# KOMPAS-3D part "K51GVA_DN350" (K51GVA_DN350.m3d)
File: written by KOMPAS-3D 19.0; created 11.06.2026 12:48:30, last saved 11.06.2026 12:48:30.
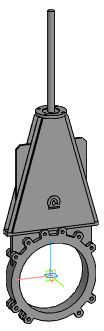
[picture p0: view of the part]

Document properties: Автор: Энергия; Полное имя файла: Z:\3.Личные\kachalov\001_3d для проектировщиков\2.6 Тип_K51GVA. Задвижка\_stp\_stp_K51GVA_DN50-DN1000_с фланцем\K51GVA_DN350.m3d

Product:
- Part/product: K51GVA_DN350

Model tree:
1. Операция без истории:1  (labels: K51GVA_DN350)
